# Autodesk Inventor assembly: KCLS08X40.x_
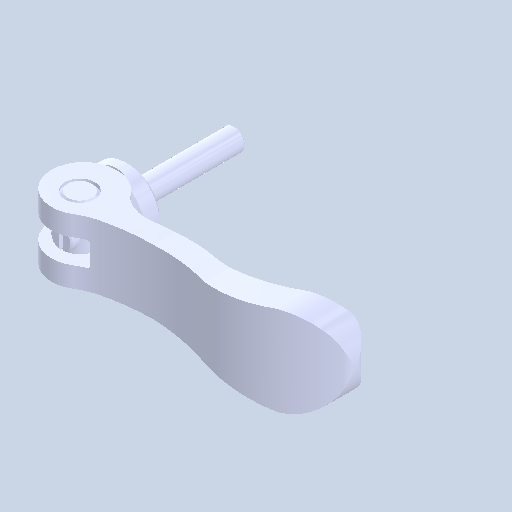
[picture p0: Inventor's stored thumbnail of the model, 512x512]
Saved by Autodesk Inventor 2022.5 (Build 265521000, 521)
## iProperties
Created: 2024-08
Part Number: KCLS08X40.x_
Document SubType Name: Assembly
Designer: ImaoCorp
Author: ImaoCorp
Sending System: SOLIDWORKS 2022-2022290
MC: AMD64
MC_MODEL: Intel64 Family 6 Model 60 Stepping 3, GenuineIntel
OS: Windows_NT
FRU: Parasolid Version 33.1, build 260,  4-25-2022
FORMAT: text
GUISE: transmit
KEY: FILEKCLS08X40.x_t
DATE: Thu Aug 29 10:55:11 2024
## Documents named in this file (5)
- Y:\5.更新分\2024年対応\1001_KCL\データ\kcls08x40\KCLS08X40.x_.iam
- Y:\5.更新分\2024年対応\1001_KCL\データ\kcls08x40\KCLS08X40_01.ipt
- Y:\5.更新分\2024年対応\1001_KCL\データ\kcls08x40\KCLS08X40_02.ipt
- Y:\5.更新分\2024年対応\1001_KCL\データ\kcls08x40\KCLS08X40_03.ipt
- Y:\5.更新分\2024年対応\1001_KCL\データ\kcls08x40\KCLS08X40_04.ipt
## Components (4 placed, 4 different names)
1. KCLS08X40_01
2. KCLS08X40_02
3. KCLS08X40_03
4. KCLS08X40_04
